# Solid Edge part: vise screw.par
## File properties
Title: Vise Screw
Author: Abhinav Rai
Template: Normal.par
Last saved by: Robert a Rhodes jr
Revision: 5
Application: Solid Edge
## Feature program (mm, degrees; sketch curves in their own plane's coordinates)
sketch for "unnamed RevolvedProtrusion 1" plane through (0, 0, 0) normal (0, -1, 0) x-axis (1, 0, 0)
  line (9.525, 77.2518) -> (9.525, 56.627)
  line (9.525, 56.627) -> (6.35, 56.627)
  line (6.35, 56.627) -> (6.35, 50.277)
  line (6.35, 50.277) -> (7.9375, 50.277)
  line (7.9375, 50.277) -> (7.9375, -49.7228)
  line (7.9375, -49.7228) -> (6.35, -49.7228)
  line (6.35, -49.7228) -> (6.35, -72.5828)
  line (6.35, -72.5828) -> (4.7625, -72.5828)
  line (4.7625, -72.5828) -> (4.7625, -75.1482)
  line (4.7625, -75.1482) -> (6.35, -75.1482)
  line (6.35, -75.1482) -> (6.35, -81.4982)
  line (6.35, -81.4982) -> (0, -81.4982)
  line (0, -81.4982) -> (0, 77.2518)
  line (0, 77.2518) -> (9.525, 77.2518)
revolve "unnamed RevolvedProtrusion 1" add finite 360 deg
sketch for "unnamed Hole 1" plane through (0, 0, 0) normal (0, -1, 0) x-axis (1, 0, 0)
  hole centre (0, 66.9394) bore radius 4.3688
hole "unnamed Hole 1" through
sketch for "unnamed Hole 2" plane through (0, 0, 0) normal (0, -1, 0) x-axis (1, 0, 0)
  hole centre (0, 66.9394) bore radius 4.3688
hole "unnamed Hole 2" through
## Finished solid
Body 1: solid body, 14 faces, 14 edges, 0 vertices.
  Faces by surface: cylinder 7, plane 7
  Edges by curve: circle 12, intersection 2
Bounding box of the edges (mm): 19.050 x 19.050 x 158.750, from (-9.525, -9.525, -81.4982) to (9.525, 9.525, 77.2518).
Cylindrical faces by radius (mm): R4.3688 x1, R4.7625 x1, R6.35 x3, R7.9375 x1, R9.525 x1
Planar faces by outward normal: +z 3, -z 4
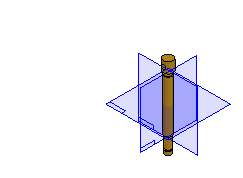
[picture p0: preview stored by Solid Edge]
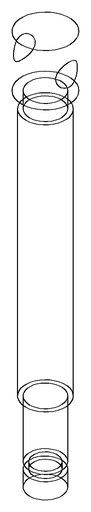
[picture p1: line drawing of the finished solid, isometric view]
